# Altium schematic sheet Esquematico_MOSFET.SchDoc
size A4
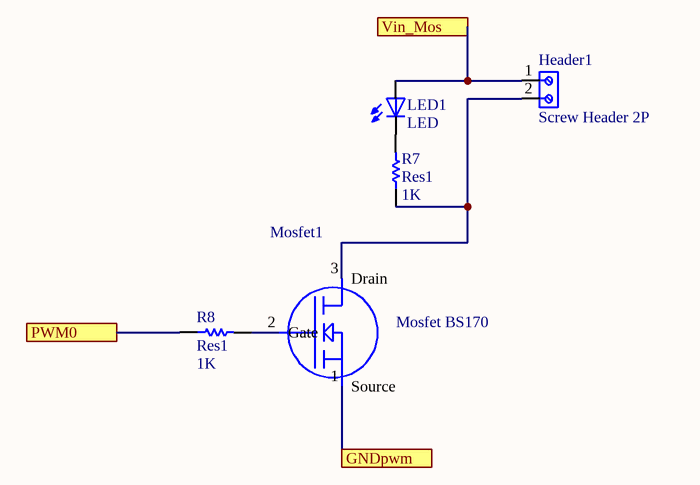
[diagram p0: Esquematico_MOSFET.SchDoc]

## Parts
Header1  Screw Header 2P  [Screw Header 2 Posicoes]
LED1  LED  [Led_THT]
Mosfet1  Mosfet BS170  [Mosfet BS170]
R7  Res1  value 1K  [AXIAL-0.3]
R8  Res1  value 1K  [AXIAL-0.3]

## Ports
GNDpwm, PWM0, Vin_Mos

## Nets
GNDpwm: Mosfet1.1(Source) ; port GNDpwm
PWM0: R8.1 ; port PWM0
Vin_Mos: Header1.1 LED1.A ; port Vin_Mos
NetHeader1_2: Header1.2 Mosfet1.3(Drain) R7.1
NetLED1_K: LED1.K(C) R7.2
NetMosfet1_2: Mosfet1.2(Gate) R8.2

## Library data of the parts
R7 R8 = Res1: Resistor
